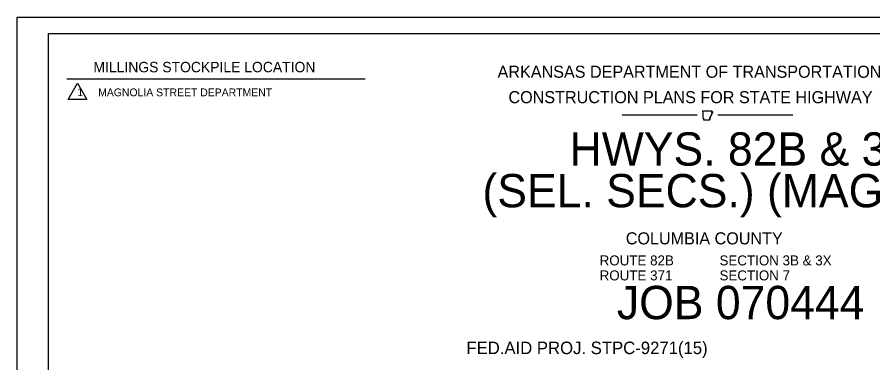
# Model space of a CAD drawing. Extents: x 61396 to 64680, y 55472 to 57605.
# Drawn here: x 61396 to 63452, y 56776 to 57605 of the extents above; entities that cross this region are included whole.
import ezdxf

# ---------------------------------------------------------------- set-up
doc = ezdxf.new("R2010")
doc.units = 0
for name, color, linetype in [('Default', 7, 'Continuous'), ('R_Draft', 7, 'Continuous'), ('R_No Plot', 7, 'Continuous')]:
    doc.layers.add(name, color=color, linetype=linetype)

msp = doc.modelspace()

# ---------------------------------------------------------------- linework, layer by layer
at = {"layer": 'Default'}
for p, q in [((61471.80410676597, 57566.00871735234), (64633.61410676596, 57566.00871735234)), ((61471.80410676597, 55511.57871735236), (61471.80410676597, 57566.00871735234)), ((61516.03001946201, 57457.616825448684), (62232.62860536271, 57457.616825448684)), ((62850.028106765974, 57371.2177173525), (63030.028106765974, 57371.2177173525)), ((63080.02810676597, 57371.2177173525), (63260.02810676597, 57371.2177173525))]:
    msp.add_line(p, q, dxfattribs=at)
for points in [[(63042.80733133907, 57380.685887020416), (63049.27533133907, 57380.68188702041), (63054.95133133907, 57380.69388702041), (63061.64733133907, 57380.79788702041), (63064.751331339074, 57380.86988702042)], [(63042.80733133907, 57380.685887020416), (63043.63533133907, 57374.03788702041), (63043.27533133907, 57363.185887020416)], [(63045.48733133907, 57362.54188702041), (63045.49533133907, 57359.30588702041), (63060.15533133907, 57359.281887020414)], [(63063.79133133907, 57377.74588702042), (63066.82733133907, 57377.90188702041)]]:
    msp.add_lwpolyline(points, dxfattribs=at)
for points in [[(63064.751331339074, 57380.86988702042), (63064.77133133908, 57380.69388702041), (63064.82733133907, 57380.60188702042), (63064.83533133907, 57380.433887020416), (63064.90333133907, 57380.36188702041), (63065.01933133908, 57380.28988702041), (63065.12333133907, 57380.17388702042), (63065.14733133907, 57380.037887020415), (63065.11533133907, 57379.89788702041), (63065.10733133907, 57379.74188702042), (63065.09133133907, 57379.605887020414), (63065.06733133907, 57379.48188702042), (63064.97133133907, 57379.38188702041), (63064.87933133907, 57379.30988702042), (63064.79533133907, 57379.22588702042), (63064.73533133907, 57379.13788702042), (63064.63133133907, 57379.04188702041), (63064.52733133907, 57378.94188702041), (63064.44333133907, 57378.85388702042), (63064.35933133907, 57378.74188702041), (63064.31933133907, 57378.61788702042), (63064.22733133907, 57378.52988702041), (63064.15533133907, 57378.44988702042), (63064.05933133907, 57378.34188702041), (63064.01133133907, 57378.23388702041), (63063.91933133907, 57378.10988702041), (63063.89933133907, 57377.98988702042), (63063.83933133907, 57377.89388702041), (63063.83533133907, 57377.87788702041)], [(63043.27533133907, 57363.185887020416), (63043.39133133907, 57363.03388702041), (63043.43933133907, 57362.925887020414), (63043.50733133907, 57362.785887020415), (63043.60733133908, 57362.72988702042), (63043.72333133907, 57362.70988702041), (63043.74733133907, 57362.57388702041), (63043.86733133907, 57362.56988702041), (63043.96333133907, 57362.59788702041), (63044.09533133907, 57362.56188702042), (63044.23533133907, 57362.65788702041), (63044.31533133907, 57362.63388702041), (63044.43133133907, 57362.681887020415), (63044.51933133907, 57362.6098870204), (63044.67133133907, 57362.67388702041), (63044.80733133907, 57362.76188702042), (63044.93533133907, 57362.67788702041), (63045.05933133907, 57362.66588702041), (63045.20733133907, 57362.645887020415), (63045.32333133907, 57362.63788702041), (63045.42733133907, 57362.58588702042), (63045.50333133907, 57362.53388702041), (63045.48733133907, 57362.54188702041)], [(63060.76733133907, 57364.79388702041), (63060.72733133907, 57364.70188702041), (63060.68333133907, 57364.541887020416), (63060.69533133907, 57364.40588702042), (63060.75533133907, 57364.28988702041), (63060.85133133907, 57364.22588702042), (63060.95533133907, 57364.13388702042), (63060.94733133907, 57363.99388702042), (63060.88733133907, 57363.94188702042), (63060.74733133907, 57363.97788702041), (63060.63933133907, 57364.02588702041), (63060.54733133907, 57363.99788702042), (63060.42333133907, 57363.93788702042), (63060.33133133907, 57363.925887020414), (63060.33533133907, 57363.73388702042), (63060.45933133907, 57363.59788702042), (63060.56733133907, 57363.59788702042), (63060.69133133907, 57363.58188702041), (63060.73533133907, 57363.43788702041), (63060.66333133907, 57363.317887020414), (63060.54333133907, 57363.257887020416), (63060.39133133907, 57363.329887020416), (63060.28333133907, 57363.40588702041), (63060.17533133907, 57363.47788702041), (63060.03933133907, 57363.51388702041), (63059.96333133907, 57363.49788702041), (63059.92733133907, 57363.329887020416), (63059.99133133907, 57363.17788702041), (63060.09533133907, 57363.073887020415), (63060.19133133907, 57362.93788702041), (63060.17533133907, 57362.83788702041), (63060.10333133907, 57362.80988702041), (63059.97533133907, 57362.78188702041), (63059.89933133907, 57362.74188702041), (63059.87933133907, 57362.70988702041), (63059.91933133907, 57362.57388702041), (63059.95533133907, 57362.425887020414), (63059.95533133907, 57362.31388702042), (63059.91133133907, 57362.20988702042), (63059.84333133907, 57362.04988702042), (63059.85133133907, 57361.94588702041), (63059.89933133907, 57361.89788702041), (63059.95933133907, 57361.91388702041), (63060.03933133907, 57361.96988702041), (63060.09133133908, 57362.03388702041), (63060.13533133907, 57362.11388702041), (63060.21933133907, 57362.181887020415), (63060.32333133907, 57362.12188702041), (63060.34733133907, 57361.99788702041), (63060.28733133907, 57361.889887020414), (63060.20333133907, 57361.84188702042), (63060.09933133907, 57361.80188702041), (63060.02333133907, 57361.71388702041), (63060.04333133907, 57361.609887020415), (63060.10333133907, 57361.55388702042), (63060.251331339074, 57361.58188702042), (63060.35133133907, 57361.62588702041), (63060.40733133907, 57361.68188702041), (63060.47533133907, 57361.749887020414), (63060.51133133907, 57361.81788702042), (63060.56333133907, 57361.889887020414), (63060.65533133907, 57361.90988702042), (63060.69933133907, 57361.84988702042), (63060.68333133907, 57361.71388702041), (63060.62733133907, 57361.58588702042), (63060.55133133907, 57361.47788702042), (63060.46733133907, 57361.4018870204), (63060.36333133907, 57361.23788702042), (63060.38333133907, 57361.08588702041), (63060.42333133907, 57360.96188702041), (63060.47933133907, 57360.86588702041), (63060.57533133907, 57360.88588702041), (63060.68333133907, 57360.89788702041), (63060.74733133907, 57360.84588702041), (63060.73933133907, 57360.73388702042), (63060.65933133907, 57360.62588702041), (63060.58333133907, 57360.52188702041), (63060.54333133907, 57360.37788702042), (63060.55933133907, 57360.27788702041), (63060.55933133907, 57360.18588702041), (63060.52733133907, 57360.08588702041), (63060.47133133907, 57360.02988702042), (63060.32333133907, 57360.03388702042), (63060.16733133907, 57360.04988702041), (63060.08333133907, 57360.001887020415), (63060.09933133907, 57359.865887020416), (63060.19133133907, 57359.76588702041), (63060.25533133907, 57359.71388702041), (63060.34733133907, 57359.60188702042), (63060.38733133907, 57359.50988702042), (63060.37533133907, 57359.429887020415), (63060.31933133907, 57359.36188702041), (63060.15533133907, 57359.281887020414)], [(63063.52333133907, 57370.08588702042), (63063.43133133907, 57369.96988702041), (63063.29533133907, 57370.04188702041), (63063.29533133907, 57370.13788702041), (63063.31533133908, 57370.23788702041), (63063.26733133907, 57370.30188702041), (63063.18333133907, 57370.27388702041), (63063.18333133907, 57370.149887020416), (63063.17533133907, 57370.02988702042), (63063.15133133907, 57369.857887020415), (63063.20733133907, 57369.80588702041), (63063.33533133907, 57369.78988702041), (63063.42733133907, 57369.76588702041), (63063.48333133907, 57369.67388702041), (63063.47933133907, 57369.56188702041), (63063.43533133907, 57369.45388702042), (63063.37133133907, 57369.36588702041), (63063.27133133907, 57369.3338870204), (63063.191331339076, 57369.38588702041), (63063.15933133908, 57369.48988702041), (63063.12333133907, 57369.58188702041), (63063.05533133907, 57369.64988702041), (63062.98333133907, 57369.57388702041), (63062.96733133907, 57369.43388702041), (63062.97133133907, 57369.31388702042), (63062.97133133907, 57369.14988702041), (63063.07533133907, 57369.04188702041), (63063.13933133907, 57368.91788702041), (63063.11933133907, 57368.80588702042), (63063.04333133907, 57368.67388702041), (63063.01133133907, 57368.55788702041), (63062.97933133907, 57368.401887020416), (63062.98333133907, 57368.22988702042), (63062.95533133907, 57368.06188702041), (63062.89933133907, 57367.94988702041), (63062.79533133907, 57367.85788702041), (63062.72733133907, 57367.79788702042), (63062.67133133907, 57367.73788702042), (63062.64333133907, 57367.61788702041), (63062.62333133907, 57367.53388702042), (63062.54733133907, 57367.43388702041), (63062.48733133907, 57367.42588702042), (63062.43933133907, 57367.46588702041), (63062.42333133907, 57367.53388702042), (63062.42333133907, 57367.60188702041), (63062.39133133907, 57367.66988702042), (63062.29133133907, 57367.69788702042), (63062.21133133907, 57367.6938870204), (63062.17533133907, 57367.63788702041), (63062.22733133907, 57367.48188702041), (63062.24733133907, 57367.38188702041), (63062.21933133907, 57367.245887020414), (63062.23533133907, 57367.22988702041), (63062.09133133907, 57367.15388702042), (63061.97533133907, 57367.14188702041), (63061.87933133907, 57367.11388702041), (63061.78733133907, 57367.05388702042), (63061.74333133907, 57366.96588702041), (63061.67933133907, 57366.893887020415), (63061.62333133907, 57366.82588702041), (63061.54733133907, 57366.79388702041), (63061.46333133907, 57366.80988702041), (63061.35133133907, 57366.821887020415), (63061.28733133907, 57366.74188702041), (63061.30733133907, 57366.62588702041), (63061.38333133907, 57366.55788702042), (63061.49533133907, 57366.52588702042), (63061.61133133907, 57366.53388702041), (63061.72333133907, 57366.5458870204), (63061.827331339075, 57366.48988702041), (63061.80733133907, 57366.38188702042), (63061.70733133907, 57366.32988702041), (63061.55933133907, 57366.313887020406), (63061.43933133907, 57366.325887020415), (63061.29533133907, 57366.293887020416), (63061.22333133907, 57366.20188702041), (63061.26333133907, 57366.06188702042), (63061.41933133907, 57366.00588702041), (63061.49133133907, 57365.87388702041), (63061.49533133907, 57365.749887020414), (63061.44333133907, 57365.58588702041), (63061.37133133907, 57365.50988702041), (63061.23133133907, 57365.47788702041), (63061.12333133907, 57365.45788702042), (63061.10733133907, 57365.27388702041), (63061.05933133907, 57365.18188702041), (63060.97533133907, 57365.15388702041), (63060.85533133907, 57365.21388702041), (63060.78333133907, 57365.24188702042), (63060.69533133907, 57365.281887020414), (63060.58333133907, 57365.34988702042), (63060.49933133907, 57365.3378870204), (63060.52333133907, 57365.16188702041), (63060.53133133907, 57365.15388702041), (63060.62733133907, 57365.02188702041), (63060.72333133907, 57364.91788702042), (63060.76733133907, 57364.79388702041)], [(63065.25933133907, 57374.04988702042), (63065.27533133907, 57373.933887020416), (63065.20733133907, 57373.80988702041), (63065.18333133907, 57373.685887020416), (63065.19533133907, 57373.56188702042), (63065.06733133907, 57373.49388702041), (63064.95533133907, 57373.41388702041), (63065.01933133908, 57373.317887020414), (63065.13933133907, 57373.22988702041), (63065.25933133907, 57373.16188702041), (63065.33533133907, 57373.09388702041), (63065.35533133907, 57372.92988702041), (63065.37533133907, 57372.82588702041), (63065.41533133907, 57372.68188702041), (63065.43133133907, 57372.58188702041), (63065.35933133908, 57372.46188702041), (63065.27533133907, 57372.4378870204), (63065.18733133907, 57372.4658870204), (63065.08333133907, 57372.47388702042), (63064.99933133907, 57372.39388702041), (63064.93933133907, 57372.281887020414), (63064.87933133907, 57372.16988702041), (63064.83533133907, 57372.073887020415), (63064.79133133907, 57371.96988702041), (63064.70333133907, 57371.84988702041), (63064.59533133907, 57371.82988702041), (63064.46733133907, 57371.79788702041), (63064.39133133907, 57371.70988702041), (63064.40333133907, 57371.56188702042), (63064.47533133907, 57371.46188702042), (63064.53133133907, 57371.33788702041), (63064.57133133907, 57371.22988702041), (63064.55133133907, 57371.09388702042), (63064.49533133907, 57370.99388702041), (63064.42333133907, 57370.93388702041), (63064.39133133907, 57370.80588702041), (63064.33933133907, 57370.70988702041), (63064.29133133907, 57370.67788702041), (63064.19533133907, 57370.685887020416), (63064.09133133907, 57370.70588702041), (63064.00333133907, 57370.69788702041), (63063.91933133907, 57370.65388702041), (63063.83533133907, 57370.6818870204), (63063.74733133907, 57370.77788702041), (63063.67533133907, 57370.84988702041), (63063.59533133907, 57370.87788702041), (63063.51133133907, 57370.83388702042), (63063.49533133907, 57370.70188702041), (63063.53533133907, 57370.56588702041), (63063.57133133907, 57370.38188702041), (63063.53533133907, 57370.26988702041), (63063.52333133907, 57370.08588702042)], [(63066.78333133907, 57377.89788702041), (63066.82733133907, 57377.90188702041), (63066.96333133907, 57377.757887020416), (63067.02333133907, 57377.63788702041), (63067.111331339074, 57377.56988702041), (63067.21133133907, 57377.53388702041), (63067.28733133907, 57377.44188702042), (63067.33933133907, 57377.34188702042), (63067.31133133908, 57377.25388702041), (63067.19933133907, 57377.24588702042), (63067.07533133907, 57377.22588702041), (63066.95533133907, 57377.22988702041), (63066.85933133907, 57377.14988702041), (63066.94733133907, 57377.041887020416), (63067.06333133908, 57376.94188702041), (63067.09533133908, 57376.8338870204), (63067.03133133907, 57376.72988702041), (63066.90333133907, 57376.67388702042), (63066.77933133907, 57376.62588702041), (63066.66733133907, 57376.52988702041), (63066.61533133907, 57376.43788702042), (63066.49133133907, 57376.39788702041), (63066.36333133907, 57376.36188702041), (63066.251331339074, 57376.34988702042), (63066.12333133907, 57376.32588702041), (63065.99933133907, 57376.26588702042), (63065.94733133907, 57376.16188702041), (63065.96333133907, 57376.01388702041), (63065.95933133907, 57375.85788702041), (63066.09133133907, 57375.80588702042), (63066.20733133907, 57375.80188702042), (63066.31933133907, 57375.74188702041), (63066.30733133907, 57375.65388702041), (63066.22333133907, 57375.541887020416), (63066.12333133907, 57375.453887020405), (63066.02333133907, 57375.40988702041), (63065.93133133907, 57375.325887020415), (63065.96333133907, 57375.24188702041), (63066.04733133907, 57375.18588702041), (63066.10733133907, 57375.09388702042), (63066.09933133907, 57375.00988702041), (63066.00333133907, 57374.94988702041), (63065.89933133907, 57374.97388702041), (63065.82333133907, 57375.07388702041), (63065.73533133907, 57375.10588702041), (63065.65933133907, 57375.141887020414), (63065.57133133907, 57375.08988702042), (63065.57133133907, 57374.97388702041), (63065.53933133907, 57374.849887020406), (63065.56733133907, 57374.75788702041), (63065.60333133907, 57374.62988702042), (63065.59933133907, 57374.53388702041), (63065.56733133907, 57374.397887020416), (63065.49933133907, 57374.257887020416), (63065.41933133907, 57374.21388702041), (63065.38733133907, 57374.365887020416), (63065.37133133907, 57374.48988702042), (63065.32333133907, 57374.56188702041), (63065.25933133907, 57374.56588702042), (63065.17533133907, 57374.50588702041), (63065.08333133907, 57374.41388702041), (63064.96733133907, 57374.31388702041), (63064.89933133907, 57374.21388702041), (63064.93533133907, 57374.08988702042), (63065.02333133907, 57374.05788702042), (63065.09133133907, 57374.08188702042), (63065.12733133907, 57374.16188702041), (63065.19533133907, 57374.17388702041), (63065.25933133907, 57374.04988702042)]]:
    msp.add_spline(points, degree=3, dxfattribs=at)
at = {"layer": 'R_Draft'}
msp.add_lwpolyline([(61541.083779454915, 57447.02099982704), (61563.60522137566, 57408.01271816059), (61518.54861432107, 57408.01271816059), (61541.07691784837, 57447.032884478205)], dxfattribs=at)
at = {"layer": 'R_No Plot'}
msp.add_lwpolyline([(61396.28410676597, 57605.47871735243), (64679.67410676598, 57605.47871735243), (64679.67410676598, 55472.1487173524), (61396.28410676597, 55472.1487173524)], close=True, dxfattribs=at)

# ---------------------------------------------------------------- texts
at = {"layer": 'Default'}
for s, height, p in [('MILLINGS STOCKPILE LOCATION', 25.000050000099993, (61579.757699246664, 57473.1269593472)), ('ARKANSAS DEPARTMENT OF TRANSPORTATION', 28.999794, (62550.58965016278, 57459.9228339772)), ('CONSTRUCTION PLANS FOR STATE HIGHWAY', 28.999794, (62576.72810676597, 57398.8692188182)), ('HWYS. 82B & 371 ', 80.00016000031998, (62723.63997763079, 57248.95471735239)), ('(SEL. SECS.) (MAGNOLIA) (S)', 80.00016000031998, (62514.190739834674, 57148.954557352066)), ('COLUMBIA COUNTY', 28.999998, (62858.559047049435, 57059.94075337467)), ('ROUTE 82B ', 24, (62795.75783474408, 57009.49558842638)), ('SECTION 3B & 3X', 24, (63083.75783474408, 57009.49558842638)), ('ROUTE 371 ', 24, (62795.75783474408, 56973.49561242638)), ('SECTION 7', 24, (63083.75783474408, 56973.49561242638)), ('JOB 070444', 80.00016000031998, (62837.19049700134, 56880.424401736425)), ('FED.AID PROJ. STPC-9271(15)', 30.00006000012, (62475.640844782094, 56796.53405624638))]:
    msp.add_text(s, height=height, dxfattribs=at).set_placement(p)
at = {"layer": 'R_Draft'}
for s, p in [('1', (61540.98079404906, 57416.1148721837)), ('MAGNOLIA STREET DEPARTMENT', (61591.00945161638, 57415.48083404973))]:
    msp.add_text(s, height=18.750035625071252, dxfattribs=at).set_placement(p)

doc.saveas('drawing.dxf')
